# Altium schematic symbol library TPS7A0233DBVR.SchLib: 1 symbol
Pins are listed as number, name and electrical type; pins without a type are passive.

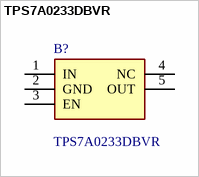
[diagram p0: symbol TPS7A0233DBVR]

## TPS7A0233DBVR
designator B?
LDO Voltage Regulators 200mA nanopower-IQ (25 nA) low-dropout; Manufacturer_Name: Texas Instruments; Geometry.Height: 1.45mm
footprint SOT95P280X145-5N
pins: 1 IN, 2 GND, 3 EN, 4 NC, 5 OUT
